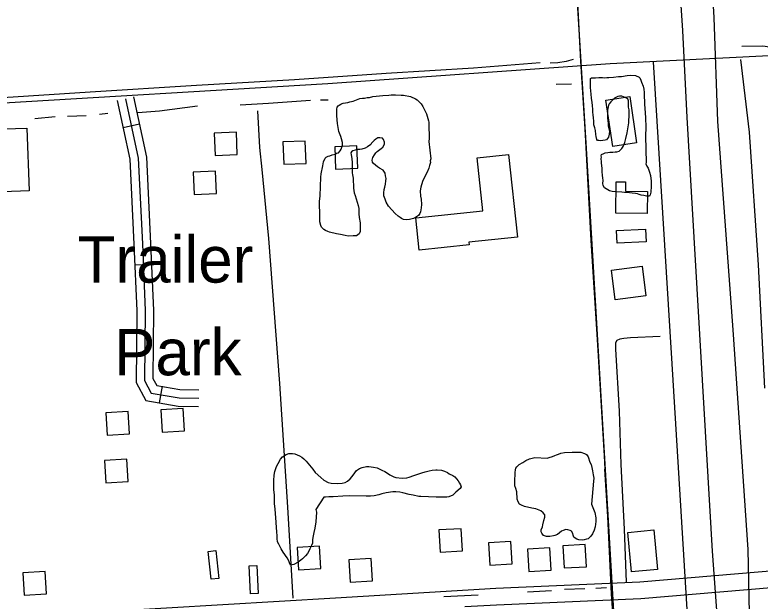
# Model space of a CAD drawing. Extents: x 3313447 to 3351316, y 703786 to 729172.
# Drawn here: x 3318120 to 3319454, y 713023 to 714073 of the extents above; entities that cross this region are included whole.
import ezdxf

# ---------------------------------------------------------------- set-up
doc = ezdxf.new("R2010")
doc.units = 0
for name, color, linetype in [('V-BLDG-IDEN', 7, 'Continuous'), ('V-BLDG-OTLN', 7, 'Continuous'), ('V-RAIL-TRAK', 7, 'Continuous'), ('V-ROAD-CNTR', 7, 'Continuous'), ('V-SITE-VEGE', 7, 'Continuous'), ('V-TOPO-SHOR', 7, 'Continuous')]:
    doc.layers.add(name, color=color, linetype=linetype)

msp = doc.modelspace()

# ---------------------------------------------------------------- linework, layer by layer
at = {"layer": 'V-BLDG-OTLN'}
for points in [[(3319190.6, 713837.4), (3319178.1, 713920), (3319220.7, 713926.5), (3319233.2, 713843.9)], [(3318141.5, 713870), (3318145.3, 713757.6), (3318003.2, 713752.7), (3318001.8, 713794.6), (3318103.2, 713798), (3318100.9, 713868.6)], [(3318516.6, 713862.9), (3318476.6, 713861.3), (3318478.2, 713821.3), (3318518.1, 713822.9)], [(3318639.8, 713847), (3318599.8, 713845.4), (3318601.4, 713805.4), (3318641.4, 713807)], [(3318732.4, 713838.3), (3318692.5, 713836.7), (3318694, 713796.7), (3318734, 713798.3)], [(3319003.9, 713822.8), (3319019.6, 713675.1), (3318932.9, 713665.9), (3318933.4, 713661.2), (3318843.8, 713651.7), (3318837.7, 713709.4), (3318957.7, 713722.1), (3318947.6, 713816.8)], [(3318479.3, 713792.8), (3318439.3, 713791.2), (3318440.8, 713751.2), (3318480.8, 713752.8)], [(3319252.3, 713717.5), (3319195.8, 713718.1), (3319196.3, 713774.2), (3319213.3, 713774), (3319213.1, 713757.3), (3319252.7, 713756.9)], [(3319250.1, 713666.4), (3319198, 713664), (3319196.9, 713687), (3319249, 713689.4)], [(3319194.8, 713562.9), (3319188.3, 713616), (3319243.3, 713622.8), (3319249.8, 713569.7)], [(3318285.3, 713320.4), (3318325.2, 713322.7), (3318322.9, 713362.6), (3318283, 713360.3)], [(3318383.7, 713325.6), (3318423.7, 713327.9), (3318421.4, 713367.9), (3318381.4, 713365.5)], [(3318282.8, 713235.1), (3318322.7, 713237.4), (3318320.4, 713277.3), (3318280.5, 713275)], [(3318881.5, 713110.4), (3318921.4, 713112.8), (3318919.1, 713152.7), (3318879.2, 713150.4)], [(3319223.9, 713075.4), (3319217.2, 713146.2), (3319263.7, 713150.6), (3319270.4, 713079.8)], [(3318970.1, 713087.4), (3319010.1, 713089.7), (3319007.7, 713129.7), (3318967.8, 713127.3)], [(3318627.7, 713079.2), (3318667.6, 713081.5), (3318665.3, 713121.4), (3318625.4, 713119.1)], [(3319040.3, 713076.2), (3319080.2, 713078.5), (3319077.9, 713118.4), (3319038, 713116.1)], [(3319103.4, 713082.4), (3319143.4, 713084.7), (3319141, 713124.6), (3319101.1, 713122.3)], [(3318471.2, 713062.3), (3318465.7, 713112), (3318479.7, 713113.5), (3318485.1, 713063.8)], [(3318720, 713056.9), (3318760, 713059.2), (3318757.7, 713099.1), (3318717.7, 713096.8)], [(3318136.6, 713033.6), (3318176.6, 713035.9), (3318174.3, 713075.8), (3318134.3, 713073.5)], [(3318541.8, 713036.1), (3318539.1, 713086), (3318553.1, 713086.7), (3318555.7, 713036.8)]]:
    msp.add_lwpolyline(points, close=True, dxfattribs=at)
at = {"layer": 'V-RAIL-TRAK'}
for points in [[(3319126.5, 714106.6), (3319132.8, 713990.2), (3319134.1, 713971.2), (3319140.1, 713868.8), (3319151.2, 713668.6), (3319163.3, 713482), (3319175.3, 713283.2), (3319176.1, 713259.2)], [(3319315.7, 710879.4), (3319300.1, 711156.1), (3319292.5, 711279.1), (3319285.9, 711372.1), (3319282.6, 711439.6), (3319268.7, 711653.2), (3319259.6, 711840.3), (3319247.4, 712032.7), (3319244, 712078.9), (3319238.2, 712215.7), (3319227.6, 712380.3), (3319223.6, 712457.3), (3319217.1, 712559.1), (3319203.4, 712778), (3319192.1, 712976.4), (3319188.4, 713035.8), (3319181.3, 713174.6), (3319176.1, 713259.2)]]:
    msp.add_lwpolyline(points, dxfattribs=at)
at = {"layer": 'V-ROAD-CNTR'}
for p, q in [((3318342.9, 713877.1), (3318313.5, 713870.8)), ((3318364.6, 713626.1), (3318334.6, 713624.8)), ((3318383.5, 713407.7), (3318378.4, 713378.1))]:
    msp.add_line(p, q, dxfattribs=at)
for points in [[(3322085.6, 717177.5), (3322015.6, 716972.5), (3322011.3, 716929.5), (3321982.2, 716607.2), (3321954.7, 716329.7), (3321908.3, 715769.3), (3321893.7, 715433.5), (3321861.3, 715083), (3321812.5, 714684.9), (3321788.9, 714463.9), (3321769.7, 714387.5), (3321726.9, 714277.1), (3321668.7, 714143.2), (3320964.4, 714096.5), (3320401.5, 714061.2), (3320028.1, 714032.5), (3319482.1, 714000.4), (3319185.8, 713985.2), (3318680.1, 713949.5), (3318059.6, 713912.2), (3317624.2, 713887.5), (3317588.3, 713886.1)], [(3319200.9, 715645.2), (3319216.7, 715284.7), (3319244.5, 714946.5), (3319270.4, 714529.8), (3319298.1, 714304.8), (3319315.2, 714045.1), (3319323.1, 713889.3), (3319368.3, 713112.6), (3319381.2, 712941.1), (3319413.2, 712432.8), (3319431.1, 712024.6), (3319452.3, 711724), (3319471.1, 711433.8), (3319475.9, 711305), (3319509.5, 710784.1), (3319530, 710456), (3319546.3, 710208.9), (3319558.3, 710026.2), (3319565.2, 709880.1), (3319575.7, 709725.1), (3319582.8, 709519.2), (3319592.9, 709284.4), (3319593.2, 709171.8)], [(3319104.4, 715556.2), (3319111.5, 715008.4), (3319106.8, 714793.8), (3319105.8, 714648.8), (3319107, 714540.6), (3319110.5, 714455.5), (3319112.5, 714365.8), (3319118.8, 714268.3), (3319122.2, 714163), (3319142.5, 713833.7), (3319173.1, 713319.1), (3319221.1, 712508.6), (3319264.3, 711756.9), (3319290.9, 711312.7), (3319362, 710097.5), (3319402.6, 709403.5), (3319416.2, 709171.5)], [(3319345.1, 714514.6), (3319371.4, 714068), (3319378, 713881.8), (3319405.6, 713508.6), (3319432.4, 713115.5), (3319435.8, 712944.4), (3319467.3, 712512), (3319484.1, 712134.4), (3319486.5, 712036.3), (3319512.8, 711766.8), (3319527.8, 711448.5), (3319527.4, 711327.4), (3319550.9, 711036.9), (3319567.8, 710785.7), (3319575.8, 710627.4), (3319594.4, 710397.1), (3319599, 710295), (3319616.4, 710052.6), (3319624.9, 709858.9), (3319631.7, 709695.3), (3319643.5, 709583.2), (3319653.2, 709388.3), (3319647.9, 709299.2), (3319653.3, 709171.9)], [(3319262.7, 713989.1), (3319296.4, 713448.2), (3319348.8, 712587.6), (3319394.3, 711836.6), (3319442.6, 710977.5), (3319493.5, 710218.9), (3319507.2, 709986.1)], [(3319462.6, 713404.7), (3319451.4, 713625.4), (3319435.1, 713863.2), (3319419.5, 713993.1)], [(3318303, 713919.7), (3318325.7, 713814.3), (3318333.1, 713662.1), (3318338.1, 713543.1), (3318336.9, 713414.5), (3318354.3, 713382.2), (3318412.3, 713372.3), (3318448.7, 713371.3)], [(3318317.7, 713922.8), (3318340.6, 713816.2), (3318348.1, 713662.8), (3318353.1, 713543.3), (3318351.9, 713418.2), (3318364, 713395.7), (3318413.8, 713387.3), (3318449.1, 713386.3)], [(3318332.3, 713926), (3318355.6, 713818.2), (3318363, 713663.5), (3318368.1, 713543.6), (3318367, 713422), (3318373.8, 713409.3), (3318415.2, 713402.2), (3318449.5, 713401.3)], [(3319720.9, 713095.9), (3319670, 713093.2), (3319238.6, 713056.7), (3318980.9, 713045.9), (3318693.7, 713028.5), (3318290.7, 713004.2), (3318030.2, 712987.7)], [(3319722.8, 713066), (3319672.1, 713063.3), (3319240.5, 713026.8), (3318982.4, 713015.9), (3318925.8, 713012.5)]]:
    msp.add_lwpolyline(points, dxfattribs=at)
at = {"layer": 'V-SITE-VEGE'}
for points in [[(3319151.6, 713930.7), (3319150.4, 713942.9), (3319150.4, 713950.9), (3319150.7, 713958.8), (3319152.1, 713960.4), (3319159.7, 713960.1), (3319165.3, 713960.6), (3319171.9, 713960.6), (3319175.2, 713960.5), (3319179.9, 713961), (3319183.2, 713960.8), (3319191.8, 713961.2), (3319200.4, 713962.5), (3319206.1, 713962.6), (3319216.4, 713964.2), (3319223, 713964.9), (3319231, 713964.6), (3319237.5, 713961.7), (3319238.7, 713960), (3319240.6, 713956), (3319241.7, 713952.3), (3319244.8, 713945.2), (3319245.9, 713939.9), (3319246.6, 713934.2), (3319246.6, 713925.6), (3319247.4, 713919.3), (3319247.5, 713913.3), (3319248.5, 713897.7), (3319248.8, 713888.5), (3319249.8, 713871.6), (3319249.2, 713856), (3319250, 713808.7)], [(3318667.9, 713695.9), (3318666.2, 713702.2), (3318666, 713706.5), (3318666.2, 713711.2), (3318665.8, 713718.1), (3318666, 713722.4), (3318665.5, 713728.1), (3318665.1, 713732.7), (3318665.3, 713738.7), (3318666.4, 713748.9), (3318667.7, 713782.2), (3318668.2, 713788.2), (3318671.5, 713802.9), (3318672.7, 713809.5), (3318675.3, 713816.3), (3318677, 713818.3), (3318681.1, 713820.1), (3318684.1, 713820.6), (3318687.8, 713822.1), (3318693.4, 713823.6), (3318695.8, 713825.1), (3318699.1, 713825.7), (3318702.6, 713829.5), (3318704.1, 713832.7), (3318706.3, 713839.6), (3318706.5, 713844.2), (3318704.8, 713851.2), (3318703.3, 713855.3), (3318699.7, 713864), (3318697.6, 713878.7), (3318697.2, 713885), (3318696.5, 713892.9), (3318696.4, 713897.9), (3318696.6, 713904.2), (3318697.1, 713907.5), (3318698.8, 713910), (3318700.5, 713911.3), (3318703.6, 713913.2), (3318705.6, 713914.1), (3318707.9, 713915), (3318711.9, 713915.5), (3318716.3, 713916.3), (3318719.6, 713917.2), (3318725.3, 713918.3), (3318728.6, 713919.8), (3318737.7, 713923.1), (3318742.4, 713923.9), (3318745.7, 713924.1), (3318750.7, 713924.9), (3318755, 713925), (3318760.7, 713926.5), (3318778.6, 713928.7), (3318789.2, 713929.3), (3318793.9, 713929.8), (3318796.9, 713929.7), (3318801.5, 713929.8), (3318811.4, 713929.4), (3318816, 713928.9), (3318828.5, 713926.8), (3318837.3, 713922.8), (3318839.9, 713921.1), (3318842.7, 713918.3), (3318847.2, 713913.5), (3318850.3, 713908.7), (3318856.7, 713895.6), (3318859.4, 713887.5), (3318860.5, 713883.5), (3318860.8, 713880.9), (3318861.3, 713878.5), (3318861.2, 713874.6), (3318861.2, 713867.3), (3318861.7, 713862), (3318861.8, 713857), (3318861.6, 713851.7), (3318861.1, 713846.1), (3318864.8, 713815.2)], [(3319250, 713808.7), (3319249.9, 713806), (3319251.7, 713802.3), (3319253.6, 713798.3), (3319255.9, 713791.2), (3319258, 713785.5), (3319258.9, 713774.9), (3319259.2, 713766.3), (3319258.8, 713755.7), (3319257.3, 713750.5), (3319256.2, 713748.2), (3319250.9, 713748.4), (3319246, 713749.6), (3319241.1, 713750.1), (3319237.5, 713751.3), (3319234.9, 713752.4), (3319230.9, 713752.9), (3319225, 713753.8), (3319220.4, 713754.3), (3319211.5, 713754.6), (3319206.9, 713755.5), (3319196, 713755.9), (3319189.1, 713756.5), (3319184.8, 713758), (3319175.7, 713763), (3319173.3, 713767.4), (3319172.7, 713770.7), (3319173, 713776.6), (3319172.8, 713780.9), (3319172, 713785.6), (3319171.3, 713792.6), (3319171.2, 713798.2), (3319170.5, 713807.2), (3319170, 713809.5), (3319169.9, 713815.8), (3319170, 713818.4), (3319169.7, 713820.8), (3319170.5, 713823.1), (3319174.5, 713824.5), (3319176.9, 713825.8), (3319181.6, 713826.6), (3319185.2, 713826.8), (3319190.8, 713826.9), (3319194.8, 713827.4), (3319197.8, 713827.6), (3319201.8, 713829.1), (3319203.5, 713830.4), (3319206.6, 713833.5), (3319208.8, 713837.1), (3319212, 713844.6), (3319214, 713851.5), (3319216, 713861.6), (3319219, 713879.4), (3319219.7, 713895.6), (3319219.6, 713903.2), (3319218.8, 713907.8), (3319218.7, 713914.5), (3319218.3, 713918.8), (3319217.1, 713922.8), (3319212.9, 713925.3), (3319206.7, 713927.2), (3319202.4, 713927.3), (3319199.4, 713926.8), (3319195.7, 713925), (3319193.6, 713923.7), (3319188.8, 713919.3), (3319187.1, 713917), (3319184, 713913.5), (3319182.9, 713911.2), (3319182.4, 713907.9), (3319181.7, 713905.7), (3319181.2, 713901), (3319181, 713896.1), (3319181, 713888.8), (3319182.3, 713878.5), (3319182.4, 713874.5), (3319184.4, 713865.5), (3319184.2, 713859.6), (3319183, 713854), (3319181.2, 713851.4), (3319179.1, 713849.2), (3319176.8, 713848.3), (3319172.5, 713847.8), (3319169.1, 713847.6), (3319165.5, 713847.7), (3319163.2, 713848.2), (3319162, 713849.9), (3319160.5, 713854.9), (3319160.3, 713858.5), (3319159.3, 713865.8), (3319158.1, 713870.8), (3319156.7, 713876.2), (3319156.6, 713881.8), (3319155.9, 713889.1), (3319155.1, 713893.5), (3319155, 713899.4), (3319154.5, 713903.7), (3319154.1, 713910.7), (3319153.3, 713916), (3319152.6, 713924), (3319151.6, 713930.7)], [(3318864.8, 713815.2), (3318863.7, 713811.3), (3318864.2, 713808.3), (3318862.4, 713803), (3318860.9, 713798.5), (3318857.9, 713791), (3318851.8, 713779), (3318849.7, 713774.4), (3318846.9, 713764.3), (3318845.7, 713757.7), (3318846.3, 713748.4), (3318847.1, 713742.8), (3318847.7, 713733.5), (3318847.5, 713727.2), (3318846.2, 713720.3), (3318845.1, 713717), (3318842.6, 713713.5), (3318836.9, 713710.1), (3318833.5, 713708.2), (3318826.5, 713706.2), (3318821.8, 713706), (3318815.6, 713706.6), (3318812.3, 713708.1), (3318809.7, 713710.2), (3318806.2, 713712.6), (3318800.8, 713717.5), (3318789, 713730.2), (3318784.7, 713737.6), (3318782.6, 713742.7), (3318780.5, 713749), (3318780.7, 713754), (3318781.3, 713760.2), (3318782.4, 713764.2), (3318783.6, 713769.7), (3318784.2, 713776), (3318784.4, 713780), (3318783.6, 713785), (3318782.7, 713789.3), (3318779.3, 713794.7), (3318772.9, 713798.6), (3318769, 713801.1), (3318761.9, 713807), (3318760.4, 713809.4), (3318759.5, 713813), (3318760.7, 713817.3), (3318763.5, 713822.5), (3318766, 713825.7), (3318768.4, 713828.2), (3318773.2, 713831.7), (3318775.9, 713833.9), (3318779, 713836.1), (3318781.8, 713841.6), (3318781.9, 713844.9), (3318780.1, 713849.6), (3318777.9, 713852.3), (3318773.3, 713852.9), (3318770, 713852.7), (3318765.9, 713850.2), (3318763.2, 713848), (3318758.7, 713843.5), (3318757, 713840.9), (3318751.5, 713836.5), (3318747.1, 713834.4), (3318741.4, 713832.3), (3318737.8, 713831.8), (3318733.1, 713831.6), (3318729.4, 713830.8), (3318725.1, 713829.6), (3318722.7, 713827.7), (3318721.6, 713825.8), (3318721.8, 713822.5), (3318722.7, 713819.1), (3318723.2, 713815.1), (3318723.6, 713808.8), (3318724, 713800.5), (3318723.8, 713795.9), (3318723.9, 713790.3), (3318724.4, 713786.3), (3318725.5, 713780.3), (3318726.1, 713762.4), (3318727.1, 713754.4), (3318728.9, 713749.7), (3318734.8, 713731.6), (3318735.6, 713726), (3318735.9, 713716.7), (3318736.6, 713710), (3318737.9, 713700.7), (3318738, 713685.2), (3318736.1, 713680.6), (3318731.7, 713677.5), (3318725.7, 713677.1), (3318716.8, 713676.8), (3318711.2, 713677.6), (3318702.7, 713679.6), (3318695.8, 713680.9), (3318683.3, 713683.7), (3318680.4, 713684.8), (3318675.8, 713687), (3318673.3, 713688.7), (3318669.1, 713692.8), (3318667.9, 713695.9)], [(3318897, 713209.8), (3318893.3, 713209), (3318889.7, 713209.1), (3318874.5, 713209), (3318846.7, 713210.1), (3318843.4, 713210.6), (3318833.3, 713213), (3318825.7, 713213.9), (3318814.6, 713217), (3318809.3, 713217.9), (3318802.1, 713218.8), (3318796.8, 713219), (3318784.5, 713217.2), (3318777.1, 713215.2), (3318771.4, 713213.4), (3318763.4, 713211.4), (3318756.7, 713210.7), (3318748.8, 713210.7), (3318719.4, 713211.8), (3318706.8, 713210.7), (3318689.9, 713209.7), (3318681.9, 713210), (3318676.3, 713209.2), (3318673.3, 713209.3), (3318658.5, 713187.1), (3318659.7, 713182.1), (3318659, 713164.9), (3318657.2, 713153.7), (3318655.3, 713145.8), (3318653.3, 713137), (3318652.8, 713132.7), (3318652.5, 713126.8), (3318651.1, 713122.8), (3318647.8, 713116.7), (3318646.4, 713112.4), (3318643.9, 713108.2), (3318640.4, 713104.1), (3318634.9, 713098.7), (3318632.1, 713096.1), (3318627.4, 713093), (3318619.3, 713088.7), (3318616.3, 713087.8), (3318613.6, 713087.6), (3318611.8, 713091.6), (3318610.6, 713095), (3318607.5, 713100.7), (3318600.3, 713110.9), (3318596.6, 713116.7), (3318592.2, 713124.8), (3318590.4, 713129.2), (3318589.7, 713135.2), (3318589.5, 713139.5), (3318588.8, 713147.8), (3318588.1, 713154.1), (3318587.5, 713164.7), (3318585.8, 713187.6), (3318584.5, 713197.6), (3318584.5, 713213.1), (3318583.8, 713222.4), (3318583.5, 713231.4), (3318583.5, 713239), (3318583.9, 713248.6), (3318585.5, 713255.4), (3318588.1, 713263.9), (3318591.3, 713269.4), (3318595.6, 713277.2), (3318599.1, 713281.4), (3318605.8, 713285.7), (3318610.2, 713287.2), (3318616.8, 713287.6), (3318621.4, 713286.8), (3318629.2, 713283.5), (3318633.4, 713280.7), (3318637.3, 713277.9), (3318641.7, 713273.4), (3318653.4, 713259.1), (3318657.8, 713253.3), (3318667.4, 713244.3), (3318672.8, 713239.4), (3318680.6, 713235.5), (3318685.9, 713234), (3318697.1, 713233.5), (3318705.7, 713234.2), (3318711.4, 713235.6), (3318715.4, 713237.8), (3318720.2, 713241.9), (3318723.7, 713246), (3318728.6, 713252.8), (3318731.4, 713257), (3318737.2, 713260.7), (3318741.9, 713262.5), (3318749.2, 713264.2), (3318753.9, 713264.1), (3318761.8, 713263.1), (3318768.3, 713261.8), (3318777.1, 713257.8), (3318782, 713255.3), (3318788.7, 713250.8), (3318791, 713249.4), (3318798.5, 713245.8), (3318801.7, 713244.6)], [(3318801.7, 713244.6), (3318813.3, 713243.5), (3318821.9, 713243.9), (3318825.9, 713245.3), (3318834.3, 713247.7), (3318848.7, 713252.7), (3318854.4, 713254.5), (3318861.8, 713256.5), (3318866.8, 713257.6), (3318873.7, 713258.4), (3318876.1, 713258.3), (3318884, 713257.3), (3318889.2, 713255.8), (3318894.4, 713253.2), (3318897.3, 713251.2), (3318903.8, 713247.9), (3318907.6, 713245.5), (3318913.3, 713238.6), (3318915.8, 713234.2), (3318918, 713231.5), (3318918.8, 713227.5), (3318917.4, 713224.9), (3318909.5, 713217.9), (3318904, 713212.8), (3318897, 713209.8)]]:
    msp.add_lwpolyline(points, dxfattribs=at)
msp.add_lwpolyline([(3319152.2, 713196.5), (3319158.2, 713181.7), (3319160.2, 713172), (3319160.3, 713165.7), (3319158.9, 713156.2), (3319157.3, 713150.3), (3319154.4, 713143.5), (3319151.3, 713139.6), (3319146.5, 713134.8), (3319143.1, 713133.7), (3319139.4, 713132.8), (3319135.8, 713132.3), (3319129.5, 713132.5), (3319126.2, 713133.7), (3319123, 713135.8), (3319120.5, 713137.8), (3319119.3, 713140.9), (3319118.7, 713143.9), (3319116.6, 713148.3), (3319114, 713149.7), (3319110, 713150.8), (3319106.4, 713151), (3319101.4, 713149.5), (3319098.4, 713148), (3319094.9, 713145.1), (3319091.2, 713142.6), (3319086.8, 713140.5), (3319084.5, 713139.9), (3319077.5, 713138.9), (3319071.9, 713138.8), (3319066.3, 713140.6), (3319063.2, 713144.7), (3319062.3, 713147.1), (3319062.4, 713150.4), (3319064.6, 713155.9), (3319065.1, 713159.9), (3319066.7, 713167.1), (3319068.6, 713173.3), (3319068.7, 713177.3), (3319065.9, 713181.3), (3319061.4, 713184.5), (3319052.6, 713188.2), (3319045.7, 713189.7), (3319032.6, 713192.6), (3319026.7, 713194.8), (3319023.5, 713196.6), (3319021, 713200.6), (3319019.2, 713205.7), (3319019.1, 713210), (3319018.6, 713215.3), (3319018.4, 713218.9), (3319016.7, 713225), (3319014.9, 713229.7), (3319014.8, 713236.9), (3319015.5, 713253.1), (3319016, 713258.4), (3319016.8, 713261), (3319018.5, 713263.3), (3319023, 713267.4), (3319029.4, 713271.4), (3319034.5, 713274.9), (3319041.3, 713277.9), (3319050.6, 713280.2), (3319073.1, 713279.3), (3319076.4, 713280.2), (3319082.5, 713282.3), (3319086.5, 713284.1), (3319089.8, 713285), (3319093.2, 713286.1), (3319097.2, 713288), (3319104.2, 713289), (3319117.5, 713289.5), (3319123.4, 713289.6), (3319129.1, 713290), (3319133.4, 713289.9), (3319139.9, 713287.6), (3319143.5, 713285.5), (3319146.3, 713281.7), (3319149.5, 713271.7), (3319151.7, 713267.6), (3319152.8, 713262.3), (3319154.2, 713256.6), (3319155.3, 713249), (3319156.4, 713243.3), (3319156.1, 713237.7)], close=True, dxfattribs=at)
at = {"layer": 'V-TOPO-SHOR'}
for p, q in [((3319116.3, 713949.1), (3319088.8, 713948)), ((3318680.9, 713920.3), (3318666.8, 713920.4)), ((3318191.9, 713890.6), (3318155.7, 713886.9)), ((3318247.6, 713892.2), (3318214.1, 713891.1)), ((3318286.5, 713896.6), (3318271.1, 713894.7)), ((3319080.9, 713041.5), (3319038, 713038.9)), ((3319140.6, 713045.1), (3319103.9, 713043.6)), ((3319179, 713046.7), (3319160.3, 713045.8)), ((3318949.6, 713033.6), (3318888.2, 713030.4))]:
    msp.add_line(p, q, dxfattribs=at)
for points in [[(3320012, 714040.7), (3319890.6, 714034.2), (3319708.2, 714022.9), (3319527, 714010.9), (3319494.2, 714010.5), (3319486.8, 714012.6), (3319459.4, 714016.8), (3319421.8, 714016.4)], [(3319060.2, 713987.1), (3318940.9, 713977.7), (3318784.9, 713968.2), (3318620.8, 713956.7), (3318445.3, 713946.7), (3318254.4, 713934.7), (3318098.4, 713924.5), (3317917.6, 713915.8), (3317713.8, 713904), (3317628.4, 713897.9)], [(3319119.3, 713993.3), (3319106.7, 713989.7), (3319091.8, 713987.3), (3319078.3, 713986.3)], [(3318649.4, 713919.9), (3318573.7, 713914.2), (3318523.3, 713911.5)], [(3318446.8, 713909.4), (3318378.7, 713900.3), (3318340.2, 713897.5)], [(3318617.9, 713028.2), (3318608.4, 713191.5), (3318594, 713412.7), (3318574.5, 713672.3), (3318562.7, 713796.1), (3318558.3, 713835.7), (3318554.7, 713901.2)], [(3319275, 713497.2), (3319222.2, 713494.7), (3319210, 713493.5), (3319202.8, 713492.1), (3319197.8, 713489.7), (3319195.6, 713485.8), (3319195.2, 713474.5), (3319201.9, 713363), (3319204.8, 713267.9), (3319210.9, 713151.9), (3319214.4, 713057.1)]]:
    msp.add_lwpolyline(points, dxfattribs=at)

# ---------------------------------------------------------------- texts
at = {"layer": 'V-BLDG-IDEN'}
for s, p in [('Trailer', (3318232.3, 713593.5)), ('Park', (3318297.5, 713427.5))]:
    msp.add_text(s, height=83, dxfattribs=at).set_placement(p)

doc.saveas('drawing.dxf')
